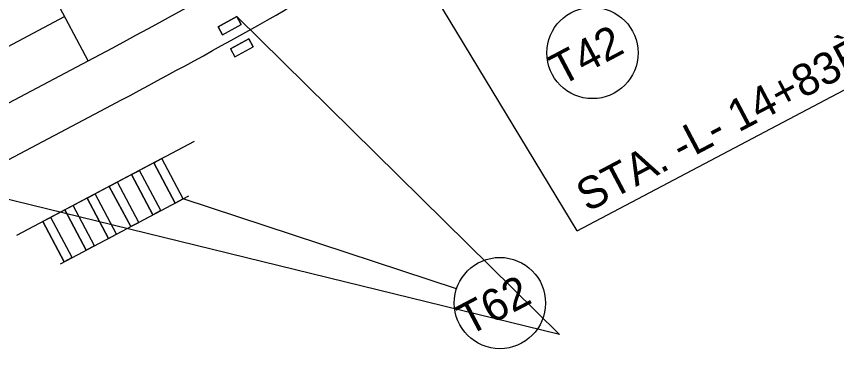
# Model space of a CAD drawing. Extents: x 1487421 to 1489048, y 497792 to 499463.
# Drawn here: x 1488099.3 to 1488279, y 498468.5 to 498545.9 of the extents above; entities that cross this region are included whole.
import ezdxf

# ---------------------------------------------------------------- set-up
doc = ezdxf.new("R2010")
doc.units = 0
for name, color, linetype in [('Prop Dimension', 7, 'Continuous'), ('Prop Mkg 3ft Min Skp 9ft White', 7, 'Continuous'), ('Prop Mkg Solid Dbl Yel Rpm 80ft', 7, 'Continuous'), ('Prop Mkg Solid Double Yellow', 7, 'Continuous'), ('Scratch_Level_3', 7, 'Continuous'), ('Scratch_Level_6', 7, 'Continuous'), ('Text', 7, 'Continuous')]:
    doc.layers.add(name, color=color, linetype=linetype)

msp = doc.modelspace()

# ---------------------------------------------------------------- linework, layer by layer
at = {"layer": 'Prop Dimension'}
msp.add_line((1488115.05, 498536.17), (1488102.41, 498560.03), dxfattribs=at)
at = {"layer": 'Prop Mkg 3ft Min Skp 9ft White'}
msp.add_line((1488015.76, 498496.06), (1488109.9, 498545.89), dxfattribs=at)
at = {"layer": 'Prop Mkg Solid Dbl Yel Rpm 80ft'}
msp.add_line((1487844.38, 498392.89), (1488115.05, 498536.17), dxfattribs=at)
at = {"layer": 'Prop Mkg Solid Double Yellow'}
msp.add_arc((1487424.96, 499839.79), 1475, 297.89497, 305.25533, dxfattribs=at)
at = {"layer": 'Scratch_Level_3'}
for p, q in [((1488143.54, 498543.58), (1488147.64, 498545.86)), ((1488147.64, 498545.86), (1488143.54, 498543.58)), ((1488147.64, 498545.86), (1488148.58, 498544.1)), ((1488148.58, 498544.1), (1488147.64, 498545.86)), ((1488218.32, 498476.2), (1488147.64, 498545.86)), ((1488144.51, 498541.83), (1488148.58, 498544.1)), ((1488144.51, 498541.83), (1488148.58, 498544.1)), ((1488144.51, 498541.83), (1488143.54, 498543.58)), ((1488143.54, 498543.58), (1488144.51, 498541.83)), ((1488146.21, 498538.77), (1488150.23, 498541.01)), ((1488150.23, 498541.01), (1488146.21, 498538.77)), ((1488150.23, 498541.01), (1488151.17, 498539.24)), ((1488151.17, 498539.24), (1488150.23, 498541.01)), ((1488146.21, 498538.77), (1488147.19, 498537.03)), ((1488147.19, 498537.03), (1488151.17, 498539.24)), ((1488147.19, 498537.03), (1488151.17, 498539.24)), ((1488218.32, 498476.2), (1488057.17, 498515.61))]:
    msp.add_line(p, q, dxfattribs=at)
at = {"layer": 'Scratch_Level_6'}
for p, q in [((1488222.16, 498498.93), (1488183.88, 498562.19)), ((1488222.16, 498498.93), (1488311, 498545.83)), ((1488066.49, 498498.02), (1488120.19, 498526.45)), ((1488099.43, 498497.92), (1488138.31, 498518.53)), ((1488131.17, 498514.74), (1488105.1, 498500.92)), ((1488129.4, 498513.8), (1488131.17, 498514.74)), ((1488131.17, 498514.74), (1488129.4, 498513.8)), ((1488134.08, 498504.97), (1488129.4, 498513.8)), ((1488129.4, 498513.8), (1488134.08, 498504.97)), ((1488135.85, 498505.91), (1488131.17, 498514.74)), ((1488135.85, 498505.91), (1488131.17, 498514.74)), ((1488124.54, 498511.23), (1488126.31, 498512.16)), ((1488126.31, 498512.16), (1488124.54, 498511.23)), ((1488130.99, 498503.33), (1488126.31, 498512.16)), ((1488130.99, 498503.33), (1488126.31, 498512.16)), ((1488121.45, 498509.59), (1488119.68, 498508.65)), ((1488121.45, 498509.59), (1488119.68, 498508.65)), ((1488126.13, 498500.75), (1488121.45, 498509.59)), ((1488126.13, 498500.75), (1488121.45, 498509.59)), ((1488129.22, 498502.39), (1488124.54, 498511.23)), ((1488124.54, 498511.23), (1488129.22, 498502.39)), ((1488124.36, 498499.82), (1488119.68, 498508.65)), ((1488119.68, 498508.65), (1488124.36, 498499.82)), ((1488108.98, 498491.66), (1488137.13, 498506.59)), ((1488114.82, 498506.08), (1488116.59, 498507.01)), ((1488116.59, 498507.01), (1488114.82, 498506.08)), ((1488119.5, 498497.24), (1488114.82, 498506.08)), ((1488114.82, 498506.08), (1488119.5, 498497.24)), ((1488121.27, 498498.18), (1488116.59, 498507.01)), ((1488121.27, 498498.18), (1488116.59, 498507.01)), ((1488111.73, 498504.44), (1488109.96, 498503.5)), ((1488111.73, 498504.44), (1488109.96, 498503.5)), ((1488116.41, 498495.6), (1488111.73, 498504.44)), ((1488116.41, 498495.6), (1488111.73, 498504.44)), ((1488135.85, 498505.91), (1488134.08, 498504.97)), ((1488134.08, 498504.97), (1488135.85, 498505.91)), ((1488195.74, 498486.2), (1488135.85, 498505.91)), ((1488114.64, 498494.66), (1488109.96, 498503.5)), ((1488109.96, 498503.5), (1488114.64, 498494.66)), ((1488130.99, 498503.33), (1488129.22, 498502.39)), ((1488129.22, 498502.39), (1488130.99, 498503.33)), ((1488106.87, 498501.86), (1488105.1, 498500.92)), ((1488106.87, 498501.86), (1488105.1, 498500.92)), ((1488109.79, 498492.09), (1488105.1, 498500.92)), ((1488105.1, 498500.92), (1488109.79, 498492.09)), ((1488111.55, 498493.03), (1488106.87, 498501.86)), ((1488111.55, 498493.03), (1488106.87, 498501.86)), ((1488126.13, 498500.75), (1488124.36, 498499.82)), ((1488124.36, 498499.82), (1488126.13, 498500.75)), ((1488119.5, 498497.24), (1488121.27, 498498.18)), ((1488119.5, 498497.24), (1488121.27, 498498.18)), ((1488116.41, 498495.6), (1488114.64, 498494.66)), ((1488114.64, 498494.66), (1488116.41, 498495.6)), ((1488111.55, 498493.03), (1488109.79, 498492.09)), ((1488109.79, 498492.09), (1488111.55, 498493.03))]:
    msp.add_line(p, q, dxfattribs=at)
msp.add_circle((1488205.24, 498483.08), 10, dxfattribs=at)
msp.add_arc((1487424.96, 499839.79), 1486, 297.89497, 300.71095, dxfattribs=at)
at = {"layer": 'Text'}
msp.add_circle((1488225.52, 498537.88), 10, dxfattribs=at)

# ---------------------------------------------------------------- texts
at = {"layer": 'Scratch_Level_6'}
for s, p in [('STA. -L- 14+83È', (1488224.41, 498502.92)), ('T62', (1488198.36, 498475.76))]:
    msp.add_text(s, height=7, rotation=27.835, dxfattribs=at).set_placement(p)
at = {"layer": 'Text'}
msp.add_text('T42', height=7, rotation=27.835, dxfattribs=at).set_placement((1488218.64, 498530.56))

doc.saveas('drawing.dxf')
